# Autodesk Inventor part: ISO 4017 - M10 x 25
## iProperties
IsCustomPart: 0
Created: 2009-02
Part Number: ISO 4017 - M10 x 25
Material: Stainless Steel, 440C
Description: Hexagon head screws
Document SubType Name: Modeling
Standard: ISO 4017
Designer: 904Chiaki
Standard Revision: Third edition 1999-08-15
Standards Organization: ISO
Language: en-US
Size Designation: M10 x 25
Categories: <MemberInstance><Categories><Category DisplayName="Fasteners" InternalName="e4da775c-781d-43d5-af7c-5136215cf5a6" Mnemonic="FSTN"><Category DisplayName="Bolts"
Density: 7.75 g/cm^3
Mass: 25.8332 g
Surface Area: 15.4943 cm^2
Volume: 3.33332 cm^3
Author: 904Chiaki
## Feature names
1. Body [Revolution]
2. Head [Extrusion]
3. Chamfer1 [Revolution]
4. Chamfer2
